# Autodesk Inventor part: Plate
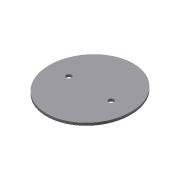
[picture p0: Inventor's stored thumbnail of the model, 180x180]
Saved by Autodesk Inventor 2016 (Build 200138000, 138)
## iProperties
Created: 2009-04
Part Number: Plate
Document SubType Name: Modeling
Designer: Sham
Density: 1 g/cm^3
Material: Generic
Appearance: Default
Author: Sham
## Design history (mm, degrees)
sketch "Sketch1"
  geometry: C1 r 6.25 at (-50, 0); C2 r 6.25 at (50, 0); 4 further points; 1 other entity
  constraints: 2 centre point, 1 coincident, 5 other
  dimensions: "d1" = 12.5 diameter of C1; "d2" = 12.5 diameter of C2; "d3" = 100 distance of C2.centre C1.centre; "d4" = 102.5 distance of point (0, 0) point (0, 102.5); "d5" = 96 distance of point (0, 0) point (-96, 0); "d6" = 50 distance of point (0, 0) C1.centre
extrude "Extrusion1" new body sketch "Sketch1" distance "d7" = 6; taper "d8" = 0 deg
body "Solid1"
